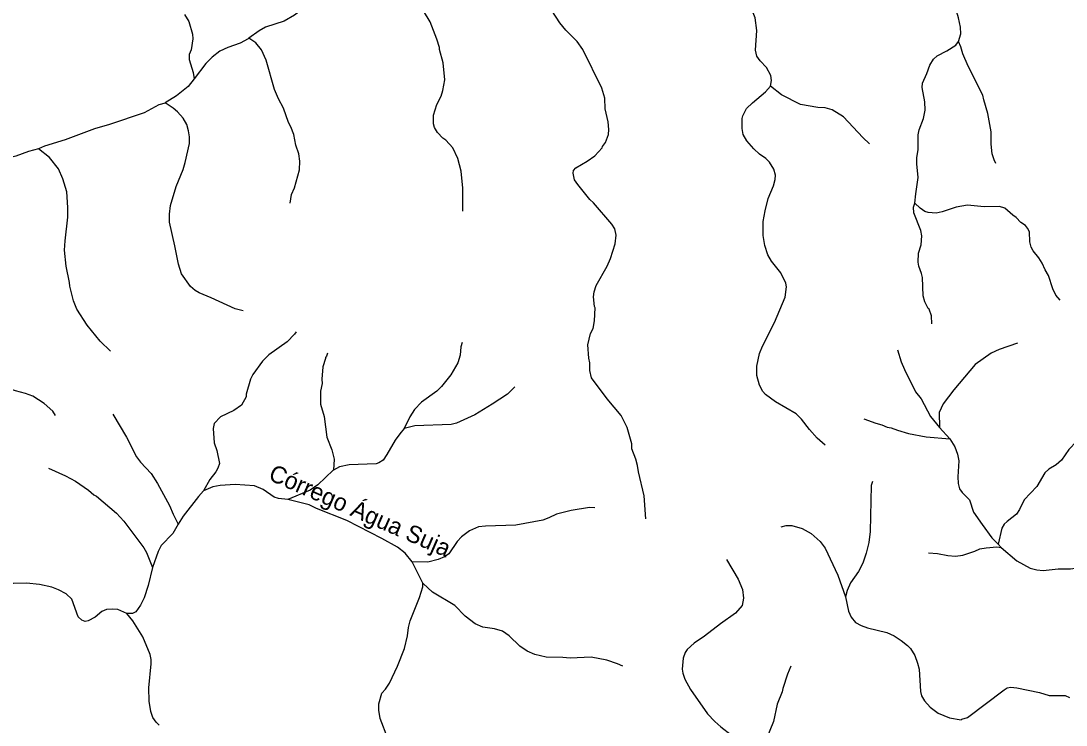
# Model space of a CAD drawing. Extents: x 500 to 555.2, y 9115.7 to 9171.
# Drawn here: x 518.44 to 528.19, y 9127.48 to 9134.05 of the extents above; entities that cross this region are included whole.
import ezdxf
from ezdxf.enums import TextEntityAlignment as Align

# ---------------------------------------------------------------- set-up
doc = ezdxf.new("R2010")
doc.units = 0
doc.header["$LTSCALE"] = 0.064
doc.layers.add('61', color=7, linetype='Continuous')
doc.layers.add('7', color=7, linetype='Continuous', lineweight=25)

msp = doc.modelspace()

# ---------------------------------------------------------------- linework, layer by layer
at = {"layer": '7'}
for p, q in [((527.01, 9130.2555), (527.1057, 9130.1484)), ((527.5563, 9129.1659), (527.5858, 9129.1349)), ((522.1903, 9128.8026), (522.0898, 9129.0033))]:
    msp.add_line(p, q, dxfattribs=at)
for points in [[(527.1883, 9133.8563), (527.2088, 9133.9293), (527.2053, 9133.9892), (527.1875, 9134.0763), (527.1435, 9134.2233), (527.1431, 9134.2877), (527.1215, 9134.4518), (527.0967, 9134.5131), (527.0737, 9134.5375), (527.0212, 9134.5582)], [(525.432, 9133.4395), (525.4423, 9133.4938), (525.4373, 9133.5393), (525.3946, 9133.6152), (525.3361, 9133.6756), (525.3054, 9133.721), (525.293, 9133.7745), (525.3044, 9133.9589), (525.2913, 9134.0763), (525.2565, 9134.1624), (525.1812, 9134.2837), (525.154, 9134.3664)], [(519.9637, 9134.109), (520.0046, 9134.0435), (520.0406, 9133.9261), (520.044, 9133.8807), (520.0277, 9133.7785), (520.0081, 9133.7367), (520.008, 9133.6899), (520.0467, 9133.5678), (520.0542, 9133.5075)], [(521.0399, 9134.1406), (520.9916, 9134.1022), (520.8964, 9134.0465), (520.7205, 9133.9895), (520.6629, 9133.9557), (520.565, 9133.8863)], [(522.5605, 9132.2727), (522.5619, 9132.4885), (522.5455, 9132.6459), (522.5139, 9132.7653), (522.4675, 9132.8636), (522.4031, 9132.9374), (522.3761, 9132.9548), (522.3249, 9133.008), (522.2978, 9133.0528), (522.2884, 9133.0888), (522.2897, 9133.1702), (522.3183, 9133.268), (522.3601, 9133.347), (522.3763, 9133.4), (522.3928, 9133.4983), (522.3781, 9133.659), (522.344, 9133.7805), (522.3435, 9133.8013), (522.3207, 9133.8794), (522.2582, 9134.0408), (522.1941, 9134.142)], [(524.2706, 9129.4046), (524.2529, 9129.6186), (524.2008, 9129.8406), (524.192, 9129.9014), (524.1756, 9129.9598), (524.1385, 9130.0568), (524.1379, 9130.1024), (524.0969, 9130.255), (524.0399, 9130.3665), (523.9092, 9130.5218), (523.7628, 9130.7193), (523.748, 9130.7878), (523.7478, 9130.8574), (523.7381, 9130.9034), (523.7299, 9131.0259), (523.7522, 9131.1313), (523.7774, 9131.1802), (523.7921, 9131.2518), (523.7971, 9131.3721), (523.7913, 9131.3832), (523.7811, 9131.4737), (523.7871, 9131.5201), (523.8053, 9131.5798), (523.9085, 9131.7619), (523.9395, 9131.8318), (523.9834, 9131.9678), (523.9936, 9132.0495), (523.9788, 9132.1085), (523.9528, 9132.1539), (523.7818, 9132.3512), (523.7475, 9132.384), (523.6343, 9132.5218), (523.6038, 9132.5674), (523.5921, 9132.6269), (523.5938, 9132.6536), (523.6155, 9132.6789), (523.721, 9132.7401), (523.793, 9132.7911), (523.8617, 9132.8636), (523.8645, 9132.8755), (523.8938, 9132.9134), (523.9216, 9132.9904), (523.9249, 9133.037), (523.9166, 9133.1058), (523.8906, 9133.2293), (523.887, 9133.3289), (523.8593, 9133.4202), (523.6831, 9133.7807), (523.6297, 9133.8564), (523.5243, 9133.9619), (523.4681, 9134.0306), (523.3931, 9134.1466)], [(520.565, 9133.8863), (520.56, 9133.8828), (520.4852, 9133.8419), (520.3706, 9133.8017), (520.2941, 9133.7665), (520.2218, 9133.7093), (520.1642, 9133.6503), (520.0542, 9133.5075)], [(520.9517, 9132.3491), (520.9632, 9132.4281), (520.9903, 9132.4918), (521.0364, 9132.6597), (521.0413, 9132.7406), (521.0311, 9132.8079), (521.0048, 9132.8907), (520.9852, 9132.9877), (520.9579, 9133.0599), (520.935, 9133.1014), (520.8871, 9133.2332), (520.8415, 9133.3214), (520.8056, 9133.4075), (520.7274, 9133.684), (520.6837, 9133.7777), (520.629, 9133.8454), (520.565, 9133.8863)], [(526.7786, 9132.347), (526.7898, 9132.4368), (526.8118, 9132.5869), (526.7988, 9132.7167), (526.7988, 9132.77), (526.8118, 9132.8487), (526.8092, 9132.9865), (526.8187, 9133.0337), (526.8614, 9133.1394), (526.8774, 9133.2175), (526.8743, 9133.2949), (526.848, 9133.4274), (526.8497, 9133.4686), (526.8922, 9133.558), (526.9205, 9133.6373), (526.9547, 9133.6908), (526.9865, 9133.7238), (527.0779, 9133.77), (527.1612, 9133.8237), (527.1883, 9133.8563)], [(527.5348, 9132.7197), (527.5186, 9132.7534), (527.5024, 9132.8073), (527.4927, 9132.898), (527.4909, 9133.0134), (527.4614, 9133.1848), (527.4227, 9133.3131), (527.4156, 9133.3572), (527.2775, 9133.6251), (527.2267, 9133.7407), (527.2086, 9133.8079), (527.1883, 9133.8563)], [(520.0542, 9133.5075), (520, 9133.4372), (519.8904, 9133.3483), (519.7853, 9133.2833)], [(525.9433, 9130.0895), (525.868, 9130.1569), (525.7974, 9130.2354), (525.7224, 9130.3333), (525.6722, 9130.3835), (525.4807, 9130.494), (525.385, 9130.5645), (525.3604, 9130.5908), (525.3308, 9130.6515), (525.3061, 9130.74), (525.3045, 9130.8285), (525.3303, 9130.9452), (525.3576, 9131.0136), (525.4717, 9131.2354), (525.5686, 9131.4722), (525.5815, 9131.5673), (525.5773, 9131.6021), (525.5308, 9131.6979), (525.4435, 9131.8067), (525.4095, 9131.8653), (525.3785, 9131.9531), (525.3635, 9132.0463), (525.3653, 9132.1775), (525.3818, 9132.2767), (525.4123, 9132.3919), (525.4597, 9132.51), (525.4762, 9132.5691), (525.48, 9132.6109), (525.4651, 9132.6655), (525.4238, 9132.73), (525.3897, 9132.764), (525.3301, 9132.8055), (525.2761, 9132.855), (525.2114, 9132.9309), (525.1785, 9132.9899), (525.1674, 9133.0453), (525.1685, 9133.138), (525.1739, 9133.1634), (525.2102, 9133.2318), (525.2646, 9133.2851), (525.3869, 9133.3863), (525.432, 9133.4395)], [(526.3557, 9132.901), (526.2932, 9132.9612), (526.1144, 9133.1548), (526.0096, 9133.2177), (525.9437, 9133.237), (525.8736, 9133.2398), (525.7129, 9133.2693), (525.5347, 9133.3592), (525.432, 9133.4395)], [(519.7853, 9133.2833), (519.7843, 9133.2827), (519.7266, 9133.2642), (519.5895, 9133.1896), (519.264, 9133.0824), (519.1243, 9133.043), (518.8506, 9132.9398), (518.6575, 9132.8807), (518.6024, 9132.8563)], [(520.5109, 9131.3449), (520.4367, 9131.3622), (520.2134, 9131.4663), (520.103, 9131.5103), (520.0649, 9131.5342), (520.0218, 9131.5707), (519.936, 9131.688), (519.9078, 9131.779), (519.8751, 9131.9505), (519.8259, 9132.171), (519.8247, 9132.2454), (519.8343, 9132.3259), (519.8871, 9132.503), (519.9521, 9132.6624), (519.9714, 9132.7266), (520.0111, 9132.9045), (520.0111, 9132.9657), (520.0033, 9133.0218), (519.9868, 9133.0817), (519.9538, 9133.1413), (519.8992, 9133.201), (519.8593, 9133.2359), (519.7853, 9133.2833)], [(518.5092, 9132.8298), (518.3898, 9132.7878), (518.2995, 9132.7643), (518.2686, 9132.7642), (518.1822, 9132.7834), (518.0324, 9132.8296), (517.9273, 9132.8334)], [(519.2729, 9130.9671), (519.1782, 9131.0613), (519.057, 9131.2086), (518.9605, 9131.3589), (518.9289, 9131.4381), (518.8945, 9131.5726), (518.8924, 9131.6067), (518.8597, 9131.7609), (518.8467, 9131.9085), (518.8516, 9131.9971), (518.8777, 9132.2189), (518.8778, 9132.3087), (518.8664, 9132.4551), (518.8302, 9132.5738), (518.7892, 9132.6689), (518.7055, 9132.7739), (518.6024, 9132.8563), (518.5092, 9132.8298)], [(526.9384, 9131.2214), (526.9365, 9131.2971), (526.9149, 9131.3598), (526.9053, 9131.3654), (526.874, 9131.4278), (526.8562, 9131.4852), (526.8498, 9131.654), (526.8416, 9131.6935), (526.8154, 9131.7597), (526.8103, 9131.7991), (526.815, 9131.8805), (526.8388, 9131.96), (526.8463, 9132.0423), (526.8365, 9132.0948), (526.7695, 9132.2582), (526.7677, 9132.3106), (526.7786, 9132.347)], [(528.1359, 9131.4447), (528.0942, 9131.4889), (528.0683, 9131.5476), (528.0273, 9131.6749), (527.9952, 9131.726), (527.9666, 9131.7897), (527.9363, 9131.8384), (527.885, 9131.9025), (527.8663, 9131.9379), (527.8519, 9131.9865), (527.8485, 9132.0806), (527.8314, 9132.1155), (527.8113, 9132.1386), (527.7674, 9132.1678), (527.7238, 9132.2145), (527.6928, 9132.2359), (527.6192, 9132.3027), (527.5697, 9132.3162), (527.428, 9132.3147), (527.2711, 9132.3309), (527.1663, 9132.3113), (527.0355, 9132.2672), (526.9786, 9132.2557), (526.9031, 9132.2624), (526.8731, 9132.2721), (526.8282, 9132.3032), (526.7786, 9132.347)], [(521.006, 9131.148), (520.9917, 9131.1264), (520.9215, 9131.0532), (520.7526, 9130.9332), (520.6915, 9130.8753), (520.6035, 9130.7498), (520.5797, 9130.7072), (520.5414, 9130.5654), (520.5394, 9130.5421), (520.4958, 9130.465), (520.4237, 9130.4131), (520.3001, 9130.3561), (520.2427, 9130.292), (520.2328, 9130.2472), (520.2407, 9130.1115), (520.2674, 9130.0399), (520.29, 9129.9192), (520.2766, 9129.8766), (520.2562, 9129.8405), (520.2023, 9129.77), (520.1433, 9129.6642)], [(522.5564, 9131.047), (522.542, 9131.0069), (522.537, 9130.9296), (522.5152, 9130.8591), (522.4507, 9130.7471), (522.3642, 9130.638), (522.3202, 9130.5933), (522.1771, 9130.493), (522.1097, 9130.4238), (522.0685, 9130.3534), (522.015, 9130.2449)], [(526.6171, 9130.98), (526.6516, 9130.8678), (526.6821, 9130.7963), (526.7871, 9130.5896), (526.8381, 9130.5217), (526.9271, 9130.3589), (527.01, 9130.2555)], [(527.7367, 9131.0423), (527.5659, 9130.984), (527.4909, 9130.9482), (527.342, 9130.8435), (527.1422, 9130.6074), (527.0432, 9130.4775), (527.0056, 9130.3965), (527.01, 9130.2555)], [(521.2977, 9130.9493), (521.2889, 9130.9195), (521.2795, 9130.9072), (521.2806, 9130.8976), (521.2563, 9130.8213), (521.2464, 9130.7051), (521.2479, 9130.6666), (521.2349, 9130.5929), (521.2352, 9130.473), (521.2675, 9130.3567), (521.2943, 9130.1644), (521.3387, 9130.0463), (521.3625, 9129.9607), (521.3538, 9129.8577)], [(528.5954, 9130.9496), (528.5689, 9130.9285), (528.5322, 9130.8838), (528.4954, 9130.8043), (528.4785, 9130.7202), (528.4621, 9130.4061), (528.4521, 9130.3595), (528.4336, 9130.3187), (528.3573, 9130.2068), (528.2881, 9130.1233), (528.2167, 9130.0486), (528.1487, 9129.9494), (528.0988, 9129.9057), (528.0299, 9129.8681), (527.9924, 9129.8326), (527.9167, 9129.706), (527.7997, 9129.5816), (527.7563, 9129.4895), (527.7288, 9129.4475), (527.6408, 9129.3793), (527.6143, 9129.3521), (527.5926, 9129.3155), (527.5563, 9129.1659)], [(518.7598, 9130.3677), (518.735, 9130.4067), (518.6564, 9130.4791), (518.5493, 9130.5473), (518.482, 9130.5728), (518.3867, 9130.5974), (518.2698, 9130.636), (518.1282, 9130.6563), (517.8228, 9130.6753)], [(523.0481, 9130.6348), (522.9783, 9130.5648), (522.837, 9130.4717), (522.6752, 9130.3741), (522.5041, 9130.2965), (522.4533, 9130.2824), (522.1148, 9130.2724), (522.015, 9130.2449)], [(519.2948, 9130.3803), (519.424, 9130.1658), (519.5179, 9129.9816), (519.5545, 9129.9319), (519.6529, 9129.8268), (519.7143, 9129.7344), (519.8253, 9129.5289), (519.8598, 9129.4453), (519.9071, 9129.3523)], [(526.3041, 9130.3373), (526.4144, 9130.2957), (526.4723, 9130.2804), (526.52, 9130.2594), (526.5582, 9130.253), (526.6172, 9130.2297), (526.7216, 9130.1991), (526.8857, 9130.1678), (527.1057, 9130.1484)], [(522.015, 9130.2449), (521.9756, 9130.1969), (521.9295, 9130.1365), (521.8537, 9130.0024), (521.8191, 9129.9508), (521.7778, 9129.9249), (521.7538, 9129.9162), (521.5007, 9129.9083), (521.4121, 9129.8885), (521.3538, 9129.8577)], [(527.1057, 9130.1484), (527.1515, 9130.0747), (527.1791, 9130.0057), (527.1891, 9129.9454), (527.181, 9129.7966), (527.1826, 9129.7335), (527.1966, 9129.6828), (527.2215, 9129.6496), (527.2904, 9129.5806), (527.3277, 9129.4663), (527.4066, 9129.3492), (527.4992, 9129.2259), (527.5563, 9129.1659)], [(518.696, 9129.8754), (518.856, 9129.8051), (518.9466, 9129.7541), (519.068, 9129.6703), (519.118, 9129.6278), (519.1439, 9129.616), (519.3305, 9129.4572), (519.3988, 9129.382), (519.5841, 9129.1342), (519.6113, 9129.0892), (519.6652, 9128.9496)], [(521.3538, 9129.8577), (521.3517, 9129.8566), (521.2105, 9129.7219), (521.1371, 9129.6692), (520.9305, 9129.5826)], [(520.9305, 9129.5826), (520.9281, 9129.5832), (520.8414, 9129.5925), (520.8025, 9129.6047), (520.6991, 9129.6782), (520.6188, 9129.7096), (520.4377, 9129.7246), (520.2981, 9129.7149), (520.2303, 9129.7013), (520.1433, 9129.6642)], [(526.3834, 9129.7523), (526.3717, 9129.713), (526.3624, 9129.2866), (526.3491, 9129.1812), (526.3261, 9129.0827), (526.2953, 9128.9904), (526.2525, 9128.9127), (526.1808, 9128.8054), (526.1495, 9128.7361), (526.1336, 9128.6757)], [(520.1433, 9129.6642), (520.0951, 9129.6103), (519.9539, 9129.4293), (519.9071, 9129.3523)], [(522.0898, 9129.0033), (522.0252, 9129.0821), (521.9519, 9129.1382), (521.8073, 9129.221), (521.4792, 9129.3867), (521.197, 9129.501), (521.1266, 9129.5343), (520.9305, 9129.5826)], [(523.7948, 9129.5071), (523.7445, 9129.508), (523.572, 9129.4821), (523.4361, 9129.4468), (523.3646, 9129.4116), (523.3098, 9129.3917), (523.0563, 9129.3441), (522.7735, 9129.3342), (522.7097, 9129.3272), (522.6232, 9129.2918), (522.5498, 9129.2351), (522.5078, 9129.1915), (522.4311, 9129.0773), (522.3899, 9129.0472), (522.3333, 9129.0224), (522.2362, 9128.9998), (522.0898, 9129.0033)], [(519.9071, 9129.3523), (519.8549, 9129.2665), (519.7467, 9129.1529), (519.719, 9129.099), (519.6652, 9128.9496)], [(525.5317, 9129.3275), (525.5796, 9129.3404), (525.6315, 9129.3407), (525.7281, 9129.3133), (525.8112, 9129.2669), (525.8965, 9129.193), (525.9425, 9129.1292), (526.0625, 9128.879), (526.1336, 9128.6757)], [(526.9076, 9129.0869), (526.9923, 9129.0798), (527.086, 9129.0617), (527.1601, 9129.0538), (527.2273, 9129.0634), (527.3384, 9129.1007), (527.3871, 9129.1239), (527.4439, 9129.1336), (527.5454, 9129.142), (527.5858, 9129.1349)], [(527.5858, 9129.1349), (527.7299, 9129.0119), (527.8571, 9128.9427), (527.9181, 9128.9273), (527.9772, 9128.9209), (528.1169, 9128.9374), (528.2331, 9128.9374), (528.3209, 9128.9487), (528.3512, 9128.947), (528.4053, 9128.9316), (528.4571, 9128.8831), (528.4764, 9128.8526), (528.5015, 9128.7931), (528.5048, 9128.6857), (528.5148, 9128.5958), (528.5157, 9128.5865)], [(525.021, 9129.0243), (525.1299, 9128.8418), (525.1707, 9128.7442), (525.1798, 9128.6627), (525.1681, 9128.5945), (525.1076, 9128.5223), (524.967, 9128.4242), (524.8167, 9128.3072), (524.7212, 9128.2443), (524.6556, 9128.1835), (524.638, 9128.1569), (524.6168, 9128.1043), (524.6074, 9128.0012), (524.6141, 9127.9642), (524.634, 9127.9079), (524.6857, 9127.8111), (524.844, 9127.5851), (524.9129, 9127.5131), (524.9709, 9127.4615), (525.0672, 9127.3885), (525.2245, 9127.2849), (525.2831, 9127.2313), (525.3255, 9127.1796)], [(519.6652, 9128.9496), (519.6262, 9128.7828), (519.5887, 9128.6649), (519.5555, 9128.5983), (519.5121, 9128.5367), (519.4783, 9128.5194), (519.4273, 9128.5192), (519.4267, 9128.5195)], [(519.4267, 9128.5195), (519.342, 9128.5565), (519.2896, 9128.5617), (519.2385, 9128.557), (519.1923, 9128.5382), (519.1312, 9128.4871), (519.0658, 9128.4517), (519.037, 9128.4469), (519.008, 9128.4564), (518.9728, 9128.4901), (518.9149, 9128.6537), (518.8614, 9128.7027), (518.7883, 9128.7417), (518.7285, 9128.765), (518.6111, 9128.7895), (518.4917, 9128.8027), (518.3659, 9128.7996), (518.2995, 9128.7801), (518.266, 9128.7782), (518.2326, 9128.7834), (518.144, 9128.8176), (518.0862, 9128.8257), (518.0252, 9128.8153), (517.907, 9128.7573)], [(521.9861, 9127.0327), (521.9544, 9127.0866), (521.8955, 9127.2245), (521.8627, 9127.3523), (521.7896, 9127.5409), (521.7779, 9127.6188), (521.7796, 9127.6759), (521.8064, 9127.7774), (521.8401, 9127.8154), (521.8762, 9127.8709), (521.9538, 9128.0297), (522.0186, 9128.1937), (522.0449, 9128.3118), (522.0548, 9128.3897), (522.0716, 9128.4507), (522.1563, 9128.6686), (522.1878, 9128.77), (522.1903, 9128.8026)], [(524.0553, 9128.0295), (524.0054, 9128.0518), (523.9057, 9128.0846), (523.7609, 9128.1121), (523.5641, 9128.1024), (523.4957, 9128.1104), (523.3398, 9128.1141), (523.2343, 9128.138), (523.1621, 9128.169), (523.0939, 9128.2151), (522.9933, 9128.3123), (522.9315, 9128.3545), (522.8584, 9128.3773), (522.7479, 9128.3926), (522.6769, 9128.4232), (522.5839, 9128.4955), (522.4884, 9128.5938), (522.2792, 9128.7196), (522.191, 9128.8012), (522.1903, 9128.8026)], [(526.1336, 9128.6757), (526.1615, 9128.5427), (526.1857, 9128.4857), (526.2274, 9128.4376), (526.2798, 9128.4077), (526.337, 9128.3869), (526.5185, 9128.3423), (526.5861, 9128.3103), (526.6524, 9128.2687), (526.7101, 9128.2221), (526.738, 9128.1926), (526.78, 9128.1267), (526.8059, 9128.0572), (526.8185, 9128), (526.8317, 9127.7934), (526.8413, 9127.752), (526.869, 9127.706), (526.9223, 9127.646), (526.9982, 9127.5909), (527.1024, 9127.5452), (527.2126, 9127.5283), (527.2193, 9127.5348), (527.2716, 9127.5486), (527.6118, 9127.8083), (527.6418, 9127.825), (527.674, 9127.8316), (527.7304, 9127.8267), (527.9437, 9127.7825), (528.0316, 9127.7549), (528.1816, 9127.7546), (528.2241, 9127.7364)], [(519.7278, 9127.477), (519.6992, 9127.5057), (519.6682, 9127.5501), (519.6518, 9127.605), (519.6358, 9127.7008), (519.6324, 9127.8279), (519.6553, 9128.0505), (519.6552, 9128.0898), (519.6454, 9128.1384), (519.5755, 9128.3013), (519.4814, 9128.4516), (519.4267, 9128.5195)], [(525.6232, 9128.0301), (525.5908, 9127.9528), (525.5474, 9127.8208), (525.5421, 9127.7891), (525.4957, 9127.674), (525.4602, 9127.5118), (525.3991, 9127.3597), (525.3567, 9127.285), (525.3255, 9127.1796)]]:
    msp.add_lwpolyline(points, dxfattribs=at)

# ---------------------------------------------------------------- texts
at = {"layer": '61'}
msp.add_text('Córrego Água Suja', height=0.16, rotation=336.371, dxfattribs=at).set_placement((521.5715, 9129.4069), align=Align.CENTER)

doc.saveas('drawing.dxf')
